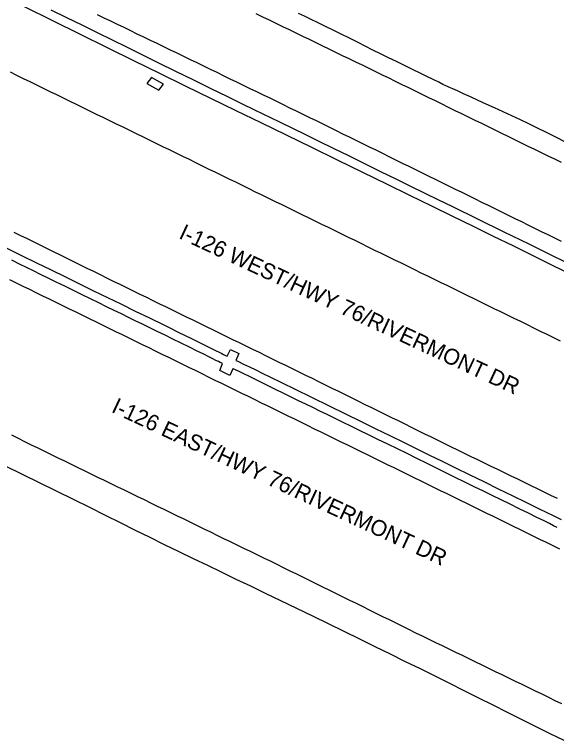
# Model space of a CAD drawing. Extents: x 1948091 to 1975253, y 787267 to 823306.
# Drawn here: x 1973771.7 to 1973955.3, y 794044.2 to 794290.3 of the extents above; entities that cross this region are included whole.
import ezdxf

# ---------------------------------------------------------------- set-up
doc = ezdxf.new("R2010")
doc.units = 0
for name, color, linetype in [('RD_EX_Pavement_Markings', 7, 'Continuous'), ('RD_EX_Road', 7, 'Continuous'), ('RD_TX_RoadID', 7, 'Continuous')]:
    doc.layers.add(name, color=color, linetype=linetype)

msp = doc.modelspace()

# ---------------------------------------------------------------- linework, layer by layer
at = {"layer": 'RD_EX_Pavement_Markings'}
for points in [[(1973799.66, 794290.32), (1973801.91, 794289.23), (1973804.16, 794288.15), (1973806.41, 794287.06), (1973808.66, 794285.97), (1973810.92, 794284.89), (1973813.17, 794283.8), (1973815.42, 794282.72), (1973817.67, 794281.63), (1973819.92, 794280.54), (1973822.17, 794279.46), (1973824.42, 794278.37), (1973826.67, 794277.28), (1973828.92, 794276.19), (1973831.17, 794275.1), (1973833.42, 794274), (1973835.67, 794272.91), (1973837.92, 794271.82), (1973840.17, 794270.73), (1973842.42, 794269.64), (1973844.66, 794268.55), (1973846.91, 794267.45), (1973849.16, 794266.36), (1973851.41, 794265.27), (1973853.66, 794264.18), (1973855.91, 794263.09), (1973858.16, 794262), (1973860.41, 794260.91), (1973862.66, 794259.81), (1973864.9, 794258.72), (1973867.15, 794257.63), (1973869.4, 794256.53), (1973871.64, 794255.42), (1973873.88, 794254.32), (1973876.12, 794253.21), (1973878.37, 794252.11), (1973880.61, 794251.01), (1973882.85, 794249.9), (1973885.1, 794248.8), (1973887.34, 794247.69), (1973889.58, 794246.59), (1973891.82, 794245.49), (1973894.07, 794244.38), (1973896.31, 794243.28), (1973898.55, 794242.17), (1973900.79, 794241.07), (1973903.04, 794239.96), (1973905.28, 794238.86), (1973907.52, 794237.76), (1973909.77, 794236.65), (1973912.01, 794235.55), (1973914.25, 794234.44), (1973916.5, 794233.34), (1973918.74, 794232.24), (1973920.98, 794231.13), (1973923.23, 794230.03), (1973925.47, 794228.93), (1973927.71, 794227.82), (1973929.96, 794226.72), (1973932.2, 794225.62), (1973934.44, 794224.51), (1973936.69, 794223.41), (1973938.93, 794222.31), (1973941.17, 794221.2), (1973943.42, 794220.1), (1973945.66, 794219), (1973947.9, 794217.89), (1973950.15, 794216.79), (1973952.39, 794215.69), (1973954.63, 794214.58), (1973956.88, 794213.48)], [(1973956.97, 794240.13), (1973954.72, 794241.23), (1973952.47, 794242.33), (1973950.23, 794243.42), (1973947.98, 794244.52), (1973945.73, 794245.61), (1973943.49, 794246.71), (1973941.24, 794247.8), (1973938.99, 794248.9), (1973936.75, 794250), (1973934.5, 794251.1), (1973932.25, 794252.2), (1973930.01, 794253.3), (1973927.76, 794254.4), (1973925.52, 794255.5), (1973923.27, 794256.6), (1973921.03, 794257.7), (1973918.78, 794258.8), (1973916.54, 794259.9), (1973914.29, 794261), (1973912.05, 794262.09), (1973909.8, 794263.19), (1973907.56, 794264.29), (1973905.31, 794265.39), (1973903.07, 794266.49), (1973900.82, 794267.59), (1973898.58, 794268.69), (1973896.33, 794269.79), (1973894.09, 794270.89), (1973891.84, 794271.99), (1973889.59, 794273.08), (1973887.34, 794274.17), (1973885.09, 794275.26), (1973882.84, 794276.35), (1973880.59, 794277.43), (1973878.34, 794278.52), (1973876.09, 794279.61), (1973873.84, 794280.7), (1973871.59, 794281.79), (1973869.34, 794282.88), (1973867.09, 794283.97), (1973864.84, 794285.06), (1973862.59, 794286.16), (1973860.35, 794287.25), (1973858.1, 794288.34), (1973855.85, 794289.43), (1973853.6, 794290.53)], [(1973956.67, 794179.57), (1973954.43, 794180.67), (1973952.18, 794181.77), (1973949.94, 794182.87), (1973947.69, 794183.97), (1973945.45, 794185.07), (1973943.2, 794186.17), (1973940.96, 794187.27), (1973938.71, 794188.37), (1973936.46, 794189.47), (1973934.22, 794190.57), (1973931.97, 794191.67), (1973929.73, 794192.77), (1973927.48, 794193.87), (1973925.24, 794194.97), (1973922.99, 794196.06), (1973920.75, 794197.16), (1973918.5, 794198.26), (1973916.26, 794199.36), (1973914.01, 794200.46), (1973911.77, 794201.56), (1973909.52, 794202.66), (1973907.28, 794203.76), (1973905.03, 794204.86), (1973902.79, 794205.96), (1973900.54, 794207.06), (1973898.3, 794208.16), (1973896.05, 794209.26), (1973893.8, 794210.35), (1973891.56, 794211.45), (1973889.31, 794212.55), (1973887.07, 794213.65), (1973884.82, 794214.75), (1973882.57, 794215.84), (1973880.33, 794216.94), (1973878.08, 794218.04), (1973875.84, 794219.14), (1973873.59, 794220.24), (1973871.34, 794221.33), (1973869.1, 794222.43), (1973866.85, 794223.53), (1973864.61, 794224.63), (1973862.36, 794225.73), (1973860.11, 794226.82), (1973857.87, 794227.92), (1973855.62, 794229.02), (1973853.38, 794230.12), (1973851.13, 794231.22), (1973848.88, 794232.32), (1973846.64, 794233.41), (1973844.39, 794234.51), (1973842.15, 794235.61), (1973839.9, 794236.71), (1973837.66, 794237.81), (1973835.41, 794238.9), (1973833.16, 794240), (1973830.92, 794241.1), (1973828.67, 794242.2), (1973826.43, 794243.3), (1973824.18, 794244.39), (1973821.93, 794245.49), (1973819.69, 794246.59), (1973817.44, 794247.69), (1973815.2, 794248.79), (1973812.95, 794249.88), (1973810.7, 794250.98), (1973808.46, 794252.08), (1973806.21, 794253.17), (1973803.96, 794254.27), (1973801.72, 794255.37), (1973799.47, 794256.46), (1973797.22, 794257.56), (1973794.98, 794258.66), (1973792.73, 794259.75), (1973790.48, 794260.85), (1973788.24, 794261.95), (1973785.99, 794263.04), (1973783.74, 794264.14), (1973781.5, 794265.24), (1973779.25, 794266.33), (1973777, 794267.43), (1973774.76, 794268.53), (1973772.51, 794269.62), (1973770.26, 794270.72)], [(1973771.48, 794216.52), (1973773.73, 794215.41), (1973775.97, 794214.31), (1973778.21, 794213.2), (1973780.45, 794212.1), (1973782.7, 794210.99), (1973784.94, 794209.89), (1973787.18, 794208.78), (1973789.42, 794207.68), (1973791.67, 794206.57), (1973793.91, 794205.47), (1973796.15, 794204.36), (1973798.39, 794203.26), (1973800.64, 794202.15), (1973802.88, 794201.05), (1973805.12, 794199.94), (1973807.37, 794198.84), (1973809.61, 794197.73), (1973811.85, 794196.63), (1973814.1, 794195.53), (1973816.34, 794194.43), (1973818.59, 794193.34), (1973820.83, 794192.24), (1973823.08, 794191.14), (1973825.33, 794190.04), (1973827.57, 794188.94), (1973829.82, 794187.85), (1973832.06, 794186.75), (1973834.31, 794185.65), (1973836.56, 794184.55), (1973838.8, 794183.46), (1973841.05, 794182.36), (1973843.3, 794181.26), (1973845.54, 794180.16), (1973847.79, 794179.06), (1973850.03, 794177.97), (1973852.28, 794176.87), (1973854.53, 794175.77), (1973856.77, 794174.67), (1973859.02, 794173.58), (1973861.26, 794172.48), (1973863.51, 794171.38), (1973865.75, 794170.28), (1973868, 794169.17), (1973870.24, 794168.07), (1973872.48, 794166.96), (1973874.72, 794165.86), (1973876.97, 794164.75), (1973879.21, 794163.65), (1973881.45, 794162.55), (1973883.7, 794161.44), (1973885.94, 794160.34), (1973888.18, 794159.23), (1973890.42, 794158.13), (1973892.67, 794157.02), (1973894.91, 794155.92), (1973897.15, 794154.82), (1973899.4, 794153.71), (1973901.64, 794152.61), (1973903.88, 794151.5), (1973906.12, 794150.4), (1973908.37, 794149.29), (1973910.61, 794148.19), (1973912.85, 794147.08), (1973915.1, 794145.98), (1973917.34, 794144.88), (1973919.58, 794143.77), (1973921.83, 794142.68), (1973924.08, 794141.59), (1973926.33, 794140.5), (1973928.58, 794139.41), (1973930.83, 794138.31), (1973933.08, 794137.22), (1973935.32, 794136.13), (1973937.57, 794135.04), (1973939.82, 794133.95), (1973942.07, 794132.85), (1973944.32, 794131.76), (1973946.57, 794130.67), (1973948.82, 794129.58), (1973951.07, 794128.49), (1973953.32, 794127.39), (1973955.57, 794126.3)], [(1973769.96, 794200.45), (1973772.21, 794199.35), (1973774.46, 794198.25), (1973776.7, 794197.15), (1973778.95, 794196.05), (1973781.19, 794194.95), (1973783.44, 794193.86), (1973785.69, 794192.76), (1973787.93, 794191.66), (1973790.18, 794190.56), (1973792.42, 794189.46), (1973794.67, 794188.37), (1973796.91, 794187.27), (1973799.16, 794186.17), (1973801.41, 794185.07), (1973803.65, 794183.97), (1973805.9, 794182.87), (1973808.14, 794181.78), (1973810.39, 794180.68), (1973812.64, 794179.58), (1973814.88, 794178.48), (1973817.13, 794177.38), (1973819.37, 794176.28), (1973821.62, 794175.18), (1973823.86, 794174.08), (1973826.11, 794172.98), (1973828.35, 794171.88), (1973830.6, 794170.78), (1973832.84, 794169.68), (1973835.09, 794168.58), (1973837.33, 794167.48), (1973839.58, 794166.38), (1973841.82, 794165.28), (1973844.07, 794164.18), (1973846.31, 794163.08), (1973848.56, 794161.98), (1973850.8, 794160.88), (1973853.05, 794159.78), (1973855.29, 794158.68), (1973857.54, 794157.58), (1973859.78, 794156.48), (1973862.03, 794155.38), (1973864.27, 794154.28), (1973866.52, 794153.18), (1973868.76, 794152.08), (1973871.01, 794150.98), (1973873.25, 794149.88), (1973875.5, 794148.78), (1973877.74, 794147.68), (1973879.99, 794146.58), (1973882.23, 794145.48), (1973884.48, 794144.38), (1973886.72, 794143.28), (1973888.97, 794142.18), (1973891.21, 794141.08), (1973893.46, 794139.98), (1973895.7, 794138.88), (1973897.95, 794137.78), (1973900.19, 794136.68), (1973902.44, 794135.58), (1973904.68, 794134.48), (1973906.93, 794133.38), (1973909.17, 794132.28), (1973911.41, 794131.18), (1973913.66, 794130.08), (1973915.9, 794128.98), (1973918.15, 794127.88), (1973920.39, 794126.78), (1973922.64, 794125.68), (1973924.88, 794124.58), (1973927.13, 794123.48), (1973929.37, 794122.38), (1973931.62, 794121.28), (1973933.86, 794120.17), (1973936.11, 794119.07), (1973938.35, 794117.97), (1973940.6, 794116.87), (1973942.84, 794115.77), (1973945.09, 794114.67), (1973947.33, 794113.57), (1973949.57, 794112.47), (1973951.82, 794111.37), (1973954.06, 794110.27), (1973956.31, 794109.17)], [(1973957.17, 794056.55), (1973954.92, 794057.64), (1973952.67, 794058.74), (1973950.42, 794059.83), (1973948.17, 794060.92), (1973945.92, 794062.01), (1973943.68, 794063.11), (1973941.43, 794064.2), (1973939.18, 794065.29), (1973936.93, 794066.38), (1973934.68, 794067.48), (1973932.43, 794068.57), (1973930.18, 794069.66), (1973927.94, 794070.76), (1973925.69, 794071.85), (1973923.44, 794072.94), (1973921.19, 794074.03), (1973918.94, 794075.13), (1973916.69, 794076.22), (1973914.44, 794077.31), (1973912.19, 794078.4), (1973909.95, 794079.5), (1973907.71, 794080.61), (1973905.47, 794081.72), (1973903.22, 794082.82), (1973900.98, 794083.93), (1973898.74, 794085.03), (1973896.5, 794086.14), (1973894.26, 794087.25), (1973892.01, 794088.35), (1973889.77, 794089.46), (1973887.53, 794090.56), (1973885.29, 794091.67), (1973883.05, 794092.78), (1973880.8, 794093.88), (1973878.56, 794094.99), (1973876.32, 794096.09), (1973874.08, 794097.2), (1973871.84, 794098.31), (1973869.59, 794099.41), (1973867.35, 794100.52), (1973865.11, 794101.63), (1973862.87, 794102.73), (1973860.62, 794103.82), (1973858.37, 794104.92), (1973856.12, 794106.01), (1973853.88, 794107.11), (1973851.63, 794108.2), (1973849.38, 794109.29), (1973847.13, 794110.39), (1973844.88, 794111.48), (1973842.64, 794112.58), (1973840.39, 794113.67), (1973838.14, 794114.77), (1973835.89, 794115.86), (1973833.65, 794116.96), (1973831.4, 794118.05), (1973829.15, 794119.15), (1973826.9, 794120.24), (1973824.66, 794121.33), (1973822.41, 794122.43), (1973820.16, 794123.52), (1973817.91, 794124.62), (1973815.67, 794125.71), (1973813.42, 794126.81), (1973811.17, 794127.9), (1973808.92, 794129), (1973806.67, 794130.09), (1973804.43, 794131.18), (1973802.18, 794132.28), (1973799.93, 794133.37), (1973797.68, 794134.47), (1973795.44, 794135.56), (1973793.19, 794136.66), (1973790.94, 794137.75), (1973788.69, 794138.85), (1973786.45, 794139.94), (1973784.2, 794141.04), (1973781.96, 794142.14), (1973779.71, 794143.24), (1973777.47, 794144.34), (1973775.22, 794145.44), (1973772.97, 794146.54), (1973770.73, 794147.64)]]:
    msp.add_lwpolyline(points, dxfattribs=at)
at = {"layer": 'RD_EX_Road'}
for points in [[(1973960.99, 794201.82), (1973953.99, 794205.24), (1973947.19, 794208.58), (1973940.59, 794211.83), (1973934, 794215.07), (1973927.21, 794218.39), (1973920.25, 794221.8), (1973913.1, 794225.29), (1973905.67, 794228.91), (1973897.86, 794232.73), (1973889.68, 794236.73), (1973881.13, 794240.91), (1973872.42, 794245.17), (1973863.79, 794249.39), (1973855.22, 794253.56), (1973846.73, 794257.7), (1973838.22, 794261.84), (1973829.62, 794266.04), (1973820.93, 794270.3), (1973812.13, 794274.63), (1973803.18, 794279.04), (1973794.01, 794283.56), (1973784.61, 794288.17), (1973775, 794292.9)], [(1973961.37, 794204.89), (1973954, 794208.48), (1973946.03, 794212.39), (1973937.62, 794216.53), (1973928.94, 794220.79), (1973919.99, 794225.18), (1973915.41, 794227.41), (1973910.77, 794229.67), (1973905.99, 794232), (1973900.99, 794234.44), (1973895.77, 794237), (1973890.34, 794239.68), (1973884.93, 794242.35), (1973879.8, 794244.87), (1973874.94, 794247.26), (1973870.36, 794249.5), (1973861.61, 794253.78), (1973853.13, 794257.9), (1973848.71, 794260.05), (1973843.78, 794262.46), (1973838.35, 794265.12), (1973832.42, 794268.04), (1973826.37, 794271.02), (1973820.61, 794273.85), (1973815.14, 794276.55), (1973809.95, 794279.11), (1973804.88, 794281.61), (1973799.77, 794284.12), (1973794.63, 794286.64), (1973789.45, 794289.16), (1973784.14, 794291.74)], [(1973958.39, 794247.07), (1973955.1, 794248.71), (1973951.93, 794250.28), (1973948.88, 794251.78), (1973945.95, 794253.21), (1973943.07, 794254.6), (1973940.17, 794255.97), (1973937.26, 794257.32), (1973934.33, 794258.66), (1973931.46, 794259.95), (1973928.75, 794261.18), (1973926.2, 794262.34), (1973923.8, 794263.44), (1973921.73, 794264.39), (1973920.14, 794265.11), (1973919.05, 794265.61), (1973918.44, 794265.88), (1973917.87, 794266.14), (1973916.86, 794266.62), (1973915.43, 794267.33), (1973913.57, 794268.24), (1973911.41, 794269.31), (1973909.07, 794270.46), (1973906.55, 794271.69), (1973903.86, 794273), (1973901.1, 794274.34), (1973898.4, 794275.67), (1973895.74, 794276.98), (1973893.12, 794278.27), (1973890.51, 794279.57), (1973887.85, 794280.9), (1973885.14, 794282.25), (1973882.38, 794283.62), (1973879.65, 794284.97), (1973877.05, 794286.26), (1973874.57, 794287.48), (1973872.2, 794288.63), (1973869.98, 794289.7), (1973867.93, 794290.7)], [(1973818.05, 794268.96), (1973816.54, 794266.89), (1973820.56, 794264.66), (1973822.1, 794266.68), (1973818.05, 794268.96)], [(1973768.82, 794211.17), (1973774.02, 794208.63), (1973779.1, 794206.14), (1973784.06, 794203.7), (1973788.92, 794201.32), (1973793.7, 794198.98), (1973798.46, 794196.66), (1973803.18, 794194.35), (1973807.88, 794192.07), (1973812.59, 794189.77), (1973817.37, 794187.44), (1973822.22, 794185.07), (1973824.34, 794184.03), (1973827.13, 794182.66), (1973831.63, 794180.46), (1973835.24, 794178.68), (1973837.95, 794177.34), (1973839.78, 794176.42), (1973840.99, 794175.81), (1973841.88, 794175.36), (1973842.45, 794175.08), (1973843.18, 794174.69), (1973843.72, 794174.44), (1973844.84, 794176.71), (1973847.67, 794175.32), (1973846.7, 794173.04), (1973847.32, 794172.75), (1973849.23, 794171.8), (1973851.26, 794170.81), (1973853.39, 794169.78), (1973855.62, 794168.7), (1973858.39, 794167.36), (1973862.1, 794165.55), (1973866.76, 794163.28), (1973872.36, 794160.53), (1973878.27, 794157.63), (1973883.87, 794154.88), (1973889.16, 794152.28), (1973894.14, 794149.84), (1973898.89, 794147.52), (1973903.49, 794145.26), (1973907.95, 794143.07), (1973912.26, 794140.95), (1973916.59, 794138.83), (1973921.09, 794136.61), (1973925.78, 794134.32), (1973930.66, 794131.93), (1973935.55, 794129.54), (1973940.3, 794127.21), (1973944.92, 794124.95), (1973949.4, 794122.76), (1973954.17, 794120.43), (1973956.9, 794119.09)], [(1973955.59, 794116.38), (1973954.35, 794117), (1973952.97, 794117.68), (1973951.09, 794118.61), (1973948.7, 794119.79), (1973945.81, 794121.2), (1973942.68, 794122.73), (1973939.59, 794124.24), (1973936.55, 794125.73), (1973933.56, 794127.2), (1973930.54, 794128.68), (1973927.45, 794130.2), (1973924.28, 794131.76), (1973921.04, 794133.35), (1973917.77, 794134.96), (1973914.49, 794136.58), (1973911.22, 794138.19), (1973907.96, 794139.81), (1973904.69, 794141.42), (1973901.42, 794143.03), (1973898.13, 794144.64), (1973894.83, 794146.25), (1973891.6, 794147.82), (1973888.52, 794149.32), (1973885.58, 794150.76), (1973882.79, 794152.12), (1973880.13, 794153.42), (1973877.57, 794154.67), (1973875.11, 794155.87), (1973872.75, 794157.01), (1973870.39, 794158.16), (1973867.93, 794159.36), (1973865.38, 794160.61), (1973862.73, 794161.92), (1973860.11, 794163.22), (1973857.67, 794164.42), (1973855.39, 794165.54), (1973853.29, 794166.56), (1973851.3, 794167.52), (1973849.38, 794168.45), (1973847.52, 794169.34), (1973845.72, 794170.19), (1973845.65, 794170.23), (1973844.58, 794167.94), (1973841.23, 794169.64), (1973842.16, 794171.96), (1973841.74, 794172.17), (1973841.34, 794172.35), (1973840.74, 794172.65), (1973839.93, 794173.05), (1973838.9, 794173.56), (1973837.56, 794174.23), (1973835.79, 794175.12), (1973833.59, 794176.21), (1973830.95, 794177.51), (1973828.13, 794178.91), (1973825.37, 794180.26), (1973822.68, 794181.58), (1973820.05, 794182.86), (1973817.48, 794184.1), (1973814.99, 794185.31), (1973812.58, 794186.48), (1973810.25, 794187.63), (1973807.89, 794188.78), (1973805.43, 794189.98), (1973802.87, 794191.24), (1973800.2, 794192.55), (1973797.44, 794193.9), (1973794.6, 794195.28), (1973791.7, 794196.71), (1973788.72, 794198.16), (1973785.79, 794199.59), (1973783.05, 794200.94), (1973780.49, 794202.19), (1973778.11, 794203.36), (1973775.77, 794204.51), (1973773.32, 794205.71), (1973770.75, 794206.97)], [(1973957.91, 794044.17), (1973952.99, 794046.59), (1973948.21, 794048.96), (1973943.48, 794051.31), (1973938.7, 794053.69), (1973933.87, 794056.11), (1973928.99, 794058.56), (1973924.07, 794061.03), (1973919.13, 794063.5), (1973914.17, 794065.96), (1973909.19, 794068.42), (1973904.16, 794070.88), (1973899.07, 794073.39), (1973893.91, 794075.92), (1973888.69, 794078.49), (1973883.42, 794081.08), (1973878.09, 794083.68), (1973872.72, 794086.29), (1973867.31, 794088.92), (1973861.95, 794091.51), (1973856.75, 794094.02), (1973851.71, 794096.45), (1973846.83, 794098.8), (1973842.02, 794101.11), (1973837.19, 794103.44), (1973832.33, 794105.79), (1973827.45, 794108.14), (1973822.53, 794110.53), (1973817.59, 794112.95), (1973812.62, 794115.41), (1973807.61, 794117.91), (1973802.49, 794120.47), (1973797.17, 794123.12), (1973791.64, 794125.87), (1973785.91, 794128.7), (1973780.1, 794131.56), (1973774.35, 794134.37), (1973768.66, 794137.14)]]:
    msp.add_lwpolyline(points, dxfattribs=at)

# ---------------------------------------------------------------- texts
at = {"layer": 'RD_TX_RoadID'}
for s, p in [('I-126 WEST/HWY 76/RIVERMONT DR', (1973827.04, 794214.57)), ('I-126 EAST/HWY 76/RIVERMONT DR', (1973804.19, 794155.65))]:
    msp.add_text(s, height=5.4, rotation=335.0005, dxfattribs=at).set_placement(p)

doc.saveas('drawing.dxf')
